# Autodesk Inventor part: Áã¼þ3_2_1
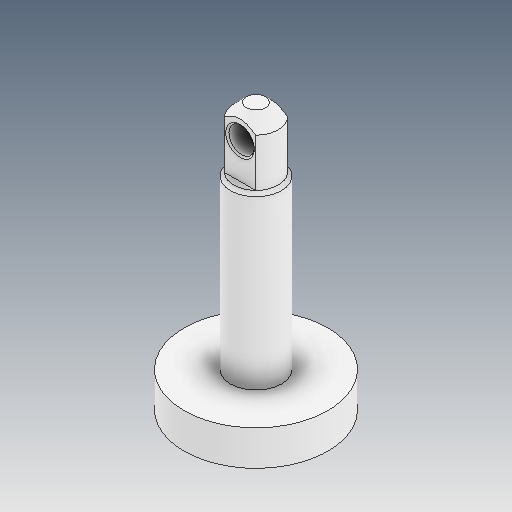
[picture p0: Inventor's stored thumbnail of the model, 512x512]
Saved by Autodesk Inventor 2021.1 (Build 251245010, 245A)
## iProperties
Created: 2021-05
Part Number: Áã¼þ3_2_1
Material: Ogólny
Document SubType Name: Modeling
Designer: user
Density: 1 g/cm^3
Appearance: Domyślna
Author: user
Revision Number: ÈÎºÎ
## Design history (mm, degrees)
feature "ÊäÈë1"
node "Bryła1"
